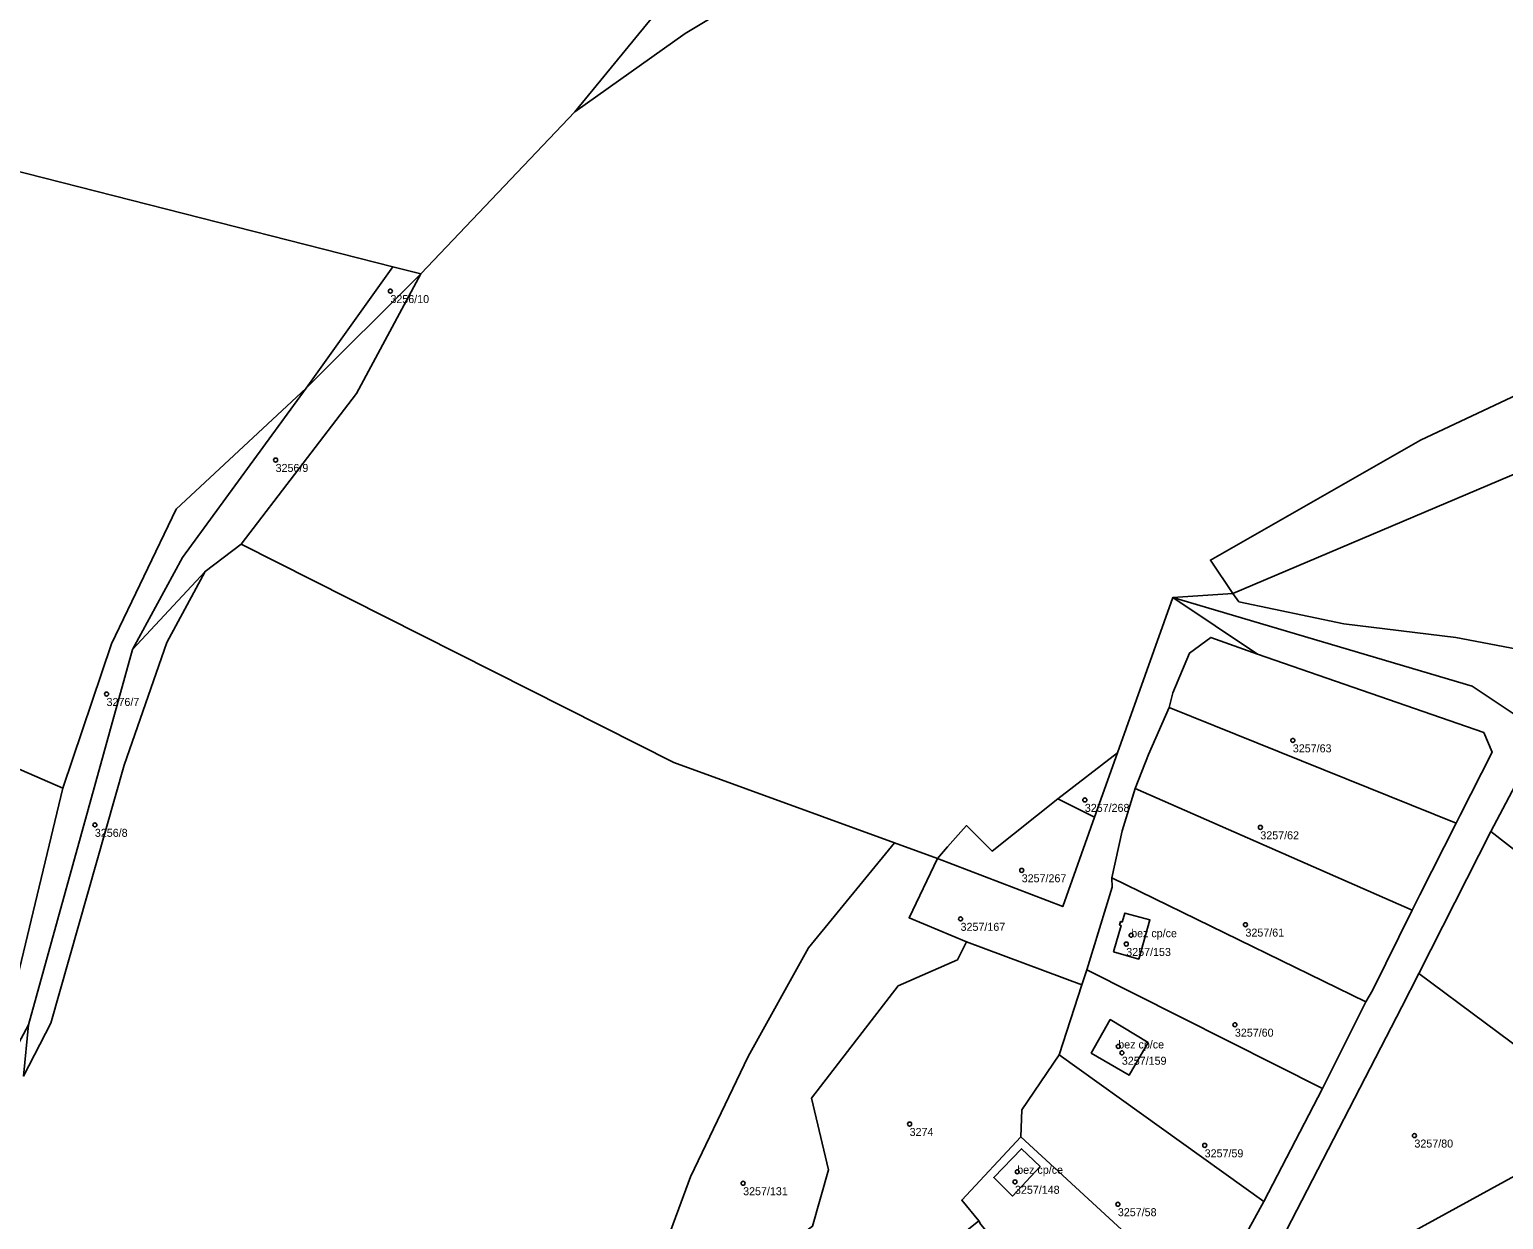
# Model space of a CAD drawing. Extents: x -878211 to -870363, y -1058464 to -1052522.
# Drawn here: x -876125.2 to -875941, y -1056558.5 to -1056409.8 of the extents above; entities that cross this region are included whole.
import ezdxf

# ---------------------------------------------------------------- set-up
doc = ezdxf.new("R2010")
doc.units = 0
for name, color, linetype in [('Definiční body', 7, 'Continuous'), ('Polygon budovy', 7, 'Continuous'), ('Polygon parcely', 7, 'Continuous')]:
    doc.layers.add(name, color=color, linetype=linetype)

msp = doc.modelspace()

# ---------------------------------------------------------------- linework, layer by layer
at = {"layer": 'Definiční body'}
for centre in [(-876080.09, -1056442.47994), (-876094.44, -1056463.58994), (-876115.57, -1056492.83994), (-875967.29, -1056498.63994), (-875993.29, -1056506.07994), (-876117.03, -1056509.19994), (-875971.35, -1056509.50994), (-876001.18, -1056514.87994), (-876008.82, -1056520.94994), (-875987.5, -1056522.98994), (-875973.21, -1056521.66994), (-875988.11, -1056524.08994), (-875974.53, -1056534.17994), (-875989.11, -1056536.88994), (-875988.66, -1056537.68994), (-876015.19, -1056546.58994), (-875952.09, -1056548.03994), (-875978.31, -1056549.25994), (-876001.74, -1056552.55994), (-876036, -1056553.99994), (-876002.02, -1056553.81994), (-875989.16, -1056556.61994)]:
    msp.add_circle(centre, 0.25, dxfattribs=at)
at = {"layer": 'Polygon budovy'}
for points in [[(-875989.7, -1056525.08), (-875986.54, -1056525.98), (-875985.15, -1056521.08), (-875988.31, -1056520.22), (-875988.63, -1056521.34), (-875988.82, -1056521.28), (-875988.95, -1056521.72), (-875988.75, -1056521.77)], [(-875990.11, -1056533.53), (-875992.49, -1056537.72), (-875987.74, -1056540.47), (-875985.39, -1056536.41)], [(-876001.2, -1056549.68), (-876004.67, -1056553.29), (-876002.34, -1056555.59), (-875998.88, -1056551.88)]]:
    msp.add_lwpolyline(points, close=True, dxfattribs=at)
at = {"layer": 'Polygon parcely'}
for points in [[(-875908.29, -1056301.21), (-875928.35, -1056301.75), (-875942.57, -1056315.35), (-875944.87, -1056319.92), (-875959.98, -1056337.05), (-875965.7, -1056343.82), (-875972.28, -1056348.38), (-875980.41, -1056358.66), (-876031.06, -1056398.23), (-876045.77, -1056406.37), (-876057.05, -1056420.08), (-876043.23, -1056410.28), (-876029.25, -1056401.81), (-875998.39, -1056377.06), (-875976.84, -1056358.72), (-875964.55, -1056344.69), (-875960.52, -1056338.33), (-875940.27, -1056318.96), (-875920.16, -1056306.35)], [(-876473.47, -1056370.01), (-876478.43, -1056375.65), (-876489.2, -1056387.89), (-876507.31, -1056415.53), (-876454, -1056421.49), (-876428.84, -1056427.3), (-876372.6, -1056439.31), (-876286.57, -1056458.81), (-876233.72, -1056470.68), (-876186.92, -1056481.7), (-876147.58, -1056493.08), (-876121.04, -1056504.6), (-876114.95, -1056486.56), (-876106.87, -1056469.73), (-876090.61, -1056454.59), (-876079.79, -1056439.45), (-876164.86, -1056417.76), (-876261.86, -1056388.42), (-876348.55, -1056363.4), (-876373.77, -1056357.39), (-876422.79, -1056348.1), (-876444.66, -1056345.92), (-876447.43, -1056347.7), (-876467.15, -1056363)], [(-876507.31, -1056415.53), (-876528.6, -1056462.59), (-876535.22, -1056470.45), (-876491.55, -1056475.96), (-876437.21, -1056488.02), (-876356.48, -1056507.94), (-876283.16, -1056524.07), (-876187.42, -1056546.21), (-876152.67, -1056554.78), (-876138.34, -1056558.36), (-876133.71, -1056549.75), (-876129.22, -1056538.47), (-876121.04, -1056504.6), (-876147.58, -1056493.08), (-876186.92, -1056481.7), (-876233.72, -1056470.68), (-876286.57, -1056458.81), (-876372.6, -1056439.31), (-876428.84, -1056427.3), (-876454, -1056421.49)], [(-876076.28, -1056440.3), (-876079.79, -1056439.45), (-876090.61, -1056454.59)], [(-875901.64, -1056442.93), (-875902.96, -1056439.22), (-875906.83, -1056440.84), (-875906.09, -1056442.83), (-875906.54, -1056447.84), (-875938.84, -1056465.02), (-875974.8, -1056480.28), (-875974.02, -1056481.33), (-875960.9, -1056484.08), (-875946.92, -1056485.76), (-875923.69, -1056490.17), (-875926.58, -1056477.79), (-875887.66, -1056453.48), (-875889.24, -1056449.96), (-875889.9, -1056448.83), (-875893.87, -1056448.89)], [(-876076.28, -1056440.3), (-876090.61, -1056454.59), (-876106.06, -1056475.76), (-876112.32, -1056487.26), (-876103.25, -1056477.52), (-876098.73, -1056474.1), (-876084.34, -1056455.28)], [(-875977.6, -1056476.09), (-875974.8, -1056480.28), (-875938.84, -1056465.02), (-875906.54, -1056447.84), (-875906.09, -1056442.83), (-875906.83, -1056440.84), (-875921.42, -1056447.02), (-875951.35, -1056461.11)], [(-876133.71, -1056549.75), (-876125.34, -1056534.17), (-876112.32, -1056487.26), (-876106.06, -1056475.76), (-876090.61, -1056454.59), (-876106.87, -1056469.73), (-876114.95, -1056486.56), (-876121.04, -1056504.6), (-876129.22, -1056538.47)], [(-876112.32, -1056487.26), (-876125.34, -1056534.17), (-876125.96, -1056540.6), (-876122.52, -1056533.99), (-876113.38, -1056501.74), (-876108.02, -1056486.39), (-876103.25, -1056477.52)], [(-875989.21, -1056500.18), (-875992.08, -1056508.24), (-875996.05, -1056519.41), (-876011.71, -1056513.39), (-876015.25, -1056520.81), (-876008.08, -1056523.8), (-875993.65, -1056529.19), (-875993.04, -1056527.32), (-875989.86, -1056516.97), (-875989.93, -1056515.82), (-875988.61, -1056509.96), (-875986.99, -1056504.66), (-875985.33, -1056500.39), (-875982.76, -1056494.51), (-875982.28, -1056492.7), (-875980.22, -1056487.72), (-875977.56, -1056485.77), (-875971.7, -1056487.87), (-875982.31, -1056480.79)], [(-875980.22, -1056487.72), (-875982.28, -1056492.7), (-875982.76, -1056494.51), (-875946.87, -1056508.97), (-875946.36, -1056507.99), (-875942.36, -1056500.09), (-875943.42, -1056497.63), (-875971.7, -1056487.87), (-875977.56, -1056485.77)], [(-875982.76, -1056494.51), (-875985.33, -1056500.39), (-875986.99, -1056504.66), (-875952.39, -1056519.84), (-875951.41, -1056517.93), (-875946.87, -1056508.97)], [(-875996.68, -1056505.95), (-875992.08, -1056508.24), (-875989.21, -1056500.18)], [(-875937.75, -1056500.73), (-875938.39, -1056502.15), (-875942.56, -1056510.03), (-875906.79, -1056537.89), (-875896.96, -1056535.43)], [(-875988.61, -1056509.96), (-875989.93, -1056515.82), (-875958.16, -1056531.33), (-875957.35, -1056529.89), (-875952.39, -1056519.84), (-875986.99, -1056504.66)], [(-875996.68, -1056505.95), (-876004.89, -1056512.47), (-876008.08, -1056509.29), (-876008.79, -1056510.06), (-876010.45, -1056511.96), (-876011.71, -1056513.39), (-875996.05, -1056519.41), (-875992.08, -1056508.24)], [(-875926.65, -1056546.29), (-875923.7, -1056544.97), (-875917.78, -1056542.73), (-875906.79, -1056537.89), (-875942.56, -1056510.03), (-875951.53, -1056527.78)], [(-875989.86, -1056516.97), (-875993.04, -1056527.32), (-875963.57, -1056542.15), (-875958.16, -1056531.33), (-875989.93, -1056515.82)], [(-875989.7, -1056525.08), (-875988.75, -1056521.77), (-875988.95, -1056521.72), (-875988.82, -1056521.28), (-875988.63, -1056521.34), (-875988.31, -1056520.22), (-875985.15, -1056521.08), (-875986.54, -1056525.98)], [(-875989.7, -1056525.08), (-875986.54, -1056525.98), (-875985.15, -1056521.08), (-875988.31, -1056520.22), (-875988.63, -1056521.34), (-875988.82, -1056521.28), (-875988.95, -1056521.72), (-875988.75, -1056521.77)], [(-876033.7, -1056579.14), (-876033.2, -1056578.86), (-876029.84, -1056576.87), (-876028.59, -1056576.22), (-876017.66, -1056567.53), (-876012.91, -1056563.82), (-876006.55, -1056558.69), (-876008.68, -1056556.1), (-876001.27, -1056548.21), (-876001.17, -1056544.81), (-875996.5, -1056537.93), (-875993.65, -1056529.19), (-876008.08, -1056523.8), (-876009.22, -1056526.08), (-876016.63, -1056529.3), (-876027.47, -1056543.35), (-876025.32, -1056552.32), (-876027.33, -1056559.37), (-876036.33, -1056566.09), (-876046.42, -1056579.75), (-876043.26, -1056583.45), (-876040.29, -1056583.07)], [(-875970.92, -1056556.29), (-875963.57, -1056542.15), (-875993.04, -1056527.32), (-875993.65, -1056529.19), (-875996.5, -1056537.93)], [(-875926.65, -1056546.29), (-875951.53, -1056527.78), (-875953.65, -1056531.96), (-875968.14, -1056559.94), (-875962.51, -1056565.65), (-875929.59, -1056547.61)], [(-875985.39, -1056536.41), (-875987.74, -1056540.47), (-875992.49, -1056537.72), (-875990.11, -1056533.53)], [(-875985.39, -1056536.41), (-875990.11, -1056533.53), (-875992.49, -1056537.72), (-875987.74, -1056540.47)], [(-876001.17, -1056544.81), (-876001.27, -1056548.21), (-875978.16, -1056569.49), (-875970.92, -1056556.29), (-875996.5, -1056537.93)], [(-876001.27, -1056548.21), (-876008.68, -1056556.1), (-876006.55, -1056558.69), (-876006.28, -1056559.16), (-875987.21, -1056581.66), (-875983.24, -1056577.61), (-875982.3, -1056576.34), (-875978.16, -1056569.49)], [(-876002.34, -1056555.59), (-876004.67, -1056553.29), (-876001.2, -1056549.68), (-875998.88, -1056551.88)], [(-876002.34, -1056555.59), (-875998.88, -1056551.88), (-876001.2, -1056549.68), (-876004.67, -1056553.29)]]:
    msp.add_lwpolyline(points, close=True, dxfattribs=at)
for points in [[(-876029.25, -1056401.81), (-876043.23, -1056410.28), (-876057.05, -1056420.08), (-876076.28, -1056440.3), (-876084.34, -1056455.28), (-876098.73, -1056474.1), (-876044.68, -1056501.38), (-876017.07, -1056511.44), (-876011.71, -1056513.39), (-876010.45, -1056511.96), (-876008.79, -1056510.06), (-876008.08, -1056509.29), (-876004.89, -1056512.47), (-875996.68, -1056505.95), (-875989.21, -1056500.18), (-875982.31, -1056480.79), (-875974.8, -1056480.28), (-875977.6, -1056476.09), (-875951.35, -1056461.11), (-875921.42, -1056447.02), (-875906.83, -1056440.84), (-875915.76, -1056419.17), (-875913.87, -1056417.81), (-875852.94, -1056386.68)], [(-876164.86, -1056417.76), (-876079.79, -1056439.45), (-876076.28, -1056440.3), (-876057.05, -1056420.08), (-876045.77, -1056406.37)], [(-876148.16, -1056700.5), (-876121.62, -1056691.73), (-876103.64, -1056686.72), (-876104.28, -1056684.6), (-876085.87, -1056679.29), (-876080.06, -1056675.29), (-876078.71, -1056672.13), (-876081.31, -1056671.52), (-876075.34, -1056648.03), (-876070.94, -1056638.08), (-876069.67, -1056630.78), (-876064.71, -1056614.32), (-876056.8, -1056591.72), (-876042.56, -1056553.18), (-876035.37, -1056538.13), (-876027.85, -1056524.56), (-876017.07, -1056511.44), (-876044.68, -1056501.38), (-876098.73, -1056474.1), (-876103.25, -1056477.52), (-876108.02, -1056486.39), (-876113.38, -1056501.74), (-876122.52, -1056533.99), (-876125.96, -1056540.6)], [(-875923.69, -1056490.17), (-875946.92, -1056485.76), (-875960.9, -1056484.08), (-875974.02, -1056481.33), (-875974.8, -1056480.28), (-875982.31, -1056480.79), (-875944.87, -1056491.87), (-875938.14, -1056496.35)], [(-875938.14, -1056496.35), (-875944.87, -1056491.87), (-875982.31, -1056480.79), (-875971.7, -1056487.87), (-875943.42, -1056497.63), (-875942.36, -1056500.09), (-875946.36, -1056507.99), (-875946.87, -1056508.97), (-875951.41, -1056517.93), (-875952.39, -1056519.84), (-875957.35, -1056529.89), (-875958.16, -1056531.33), (-875963.57, -1056542.15), (-875970.92, -1056556.29), (-875978.16, -1056569.49)], [(-875929.59, -1056547.61), (-875962.51, -1056565.65), (-875968.14, -1056559.94), (-875953.65, -1056531.96), (-875951.53, -1056527.78), (-875942.56, -1056510.03), (-875938.39, -1056502.15)], [(-876027.33, -1056559.37), (-876025.32, -1056552.32), (-876027.47, -1056543.35), (-876016.63, -1056529.3), (-876009.22, -1056526.08), (-876008.08, -1056523.8), (-876015.25, -1056520.81), (-876011.71, -1056513.39), (-876017.07, -1056511.44), (-876027.85, -1056524.56), (-876035.37, -1056538.13), (-876042.56, -1056553.18), (-876056.8, -1056591.72)]]:
    msp.add_lwpolyline(points, dxfattribs=at)

# ---------------------------------------------------------------- texts
at = {"layer": 'Definiční body'}
for s, p in [('3256/10', (-876080.09, -1056443.969)), ('3256/9', (-876094.44, -1056465.079)), ('3276/7', (-876115.57, -1056494.329)), ('3257/63', (-875967.29, -1056500.129)), ('3257/268', (-875993.29, -1056507.569)), ('3256/8', (-876117.03, -1056510.689)), ('3257/62', (-875971.35, -1056510.999)), ('3257/267', (-876001.18, -1056516.369)), ('3257/167', (-876008.82, -1056522.439)), ('bez cp/ce', (-875987.5, -1056523.24)), ('3257/61', (-875973.21, -1056523.159)), ('3257/153', (-875988.11, -1056525.579)), ('bez cp/ce', (-875989.11, -1056537.139)), ('3257/60', (-875974.53, -1056535.669)), ('3257/159', (-875988.66, -1056539.179)), ('3274', (-876015.19, -1056548.079)), ('3257/80', (-875952.09, -1056549.529)), ('3257/59', (-875978.31, -1056550.749)), ('bez cp/ce', (-876001.74, -1056552.81)), ('3257/131', (-876036, -1056555.489)), ('3257/148', (-876002.02, -1056555.309)), ('3257/58', (-875989.16, -1056558.109))]:
    msp.add_text(s, height=0.999996, dxfattribs=at).set_placement(p)

doc.saveas('drawing.dxf')
